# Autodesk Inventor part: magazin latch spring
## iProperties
Created: 2006-04
Part Number: magazin latch spring
Document SubType Name: Modeling
Designer: Калинин
Author: Калинин
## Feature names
1. Пружина1
